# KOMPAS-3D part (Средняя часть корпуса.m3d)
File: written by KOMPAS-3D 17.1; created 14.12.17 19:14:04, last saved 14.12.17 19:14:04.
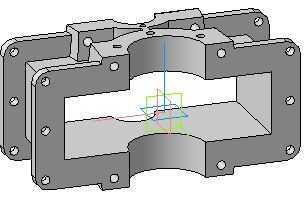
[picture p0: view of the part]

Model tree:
1. Операция без истории:1

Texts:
  Средняя часть корпуса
